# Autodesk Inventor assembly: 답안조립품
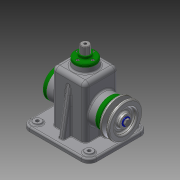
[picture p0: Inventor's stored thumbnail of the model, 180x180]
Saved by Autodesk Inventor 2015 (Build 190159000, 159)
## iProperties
Created: 2016-02
Part Number: 답안조립품
Document SubType Name: Assembly
Designer: Administrator
Author: Administrator
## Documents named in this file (19)
- C:\Users\Administrator\Desktop\460219V1013\답안조립품.iam
- C:\Users\Administrator\Desktop\460219V1013\본체.ipt
- C:\Users\Administrator\Desktop\460219V1013\V-벨트풀리.ipt
- C:\Users\Administrator\Desktop\460219V1013\고정핀.ipt
- C:\Users\Administrator\Desktop\460219V1013\뒤커버.ipt
- C:\Users\Administrator\Desktop\460219V1013\링크.ipt
- C:\Users\Administrator\Desktop\460219V1013\멈춤링 6 x 5.ipt
- C:\Users\Administrator\Desktop\460219V1013\멈춤링 15 x 1.ipt
- C:\Users\Administrator\Desktop\460219V1013\베어링 15 x 35 x 11.ipt
- C:\Users\Administrator\Desktop\460219V1013\볼트 M3 x 8.ipt
- C:\Users\Administrator\Desktop\460219V1013\볼트 M4 x 10.ipt
- C:\Users\Administrator\Desktop\460219V1013\볼트 M6 x 12.ipt
- C:\Users\Administrator\Desktop\460219V1013\상부부시.ipt
- C:\Users\Administrator\Desktop\460219V1013\슬라이드바.ipt
- C:\Users\Administrator\Desktop\460219V1013\앞커버.ipt
- C:\Users\Administrator\Desktop\460219V1013\오일실 15 25 7.ipt
- C:\Users\Administrator\Desktop\460219V1013\와셔.ipt
- C:\Users\Administrator\Desktop\460219V1013\키 5 x 5 x 14.ipt
- C:\Users\Administrator\Desktop\460219V1013\편심축.ipt
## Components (15 placed, 5 different names)
1. V-벨트풀리:1
2. 고정핀:1
3. ISO 4018 M6 x 12:1
4. ISO 4762 M3 x 8:1
5. ISO 4762 M3 x 8:2
6. ISO 4762 M3 x 8:3
7. ISO 4762 M3 x 8:4
8. ISO 4762 M4 x 10:1
9. ISO 4762 M4 x 10:3
10. ISO 4762 M4 x 10:4
11. ISO 4762 M4 x 10:5
12. ISO 4762 M4 x 10:2
13. ISO 4762 M4 x 10:6
14. ISO 4762 M4 x 10:7
15. ISO 4762 M4 x 10:8
